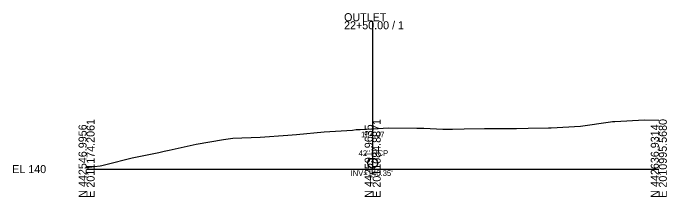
# Model space of a CAD drawing. Extents: x -26 to 1203, y -15 to 9526.
# Drawn here: x 974.3 to 1202.8, y 2490.3 to 2554.4 of the extents above; entities that cross this region are included whole.
import ezdxf

# ---------------------------------------------------------------- set-up
doc = ezdxf.new("R2010")
doc.units = 0
for name, color, linetype in [('Exist Cross Section Cell', 7, 'Continuous'), ('Exist XS Center Line Elevation Label', 7, 'Continuous'), ('Exist XS Ground Line', 7, 'Continuous'), ('Prop XSC Text', 7, 'Continuous')]:
    doc.layers.add(name, color=color, linetype=linetype)

msp = doc.modelspace()

# ---------------------------------------------------------------- linework, layer by layer
at = {"layer": 'Exist Cross Section Cell'}
for p, q in [((1100, 2500), (1100, 2551.58)), ((1000, 2500), (1100, 2500)), ((1100, 2500), (1200, 2500))]:
    msp.add_line(p, q, dxfattribs=at)
at = {"layer": 'Exist XS Ground Line'}
msp.add_lwpolyline([(1000, 2500.6), (1002.71, 2500.91), (1004.71, 2501.15), (1005.37, 2501.23), (1006.68, 2501.56), (1015.9, 2503.96), (1025.26, 2505.85), (1027.1, 2506.25), (1028.92, 2506.66), (1038.3, 2508.75), (1047.8, 2510.31), (1049.49, 2510.59), (1051.16, 2510.77), (1060.69, 2511.16), (1070.35, 2511.87), (1071.88, 2511.99), (1073.4, 2512.11), (1083.08, 2512.97), (1092.9, 2513.64), (1094.28, 2513.76), (1095.63, 2513.83), (1100, 2514.07), (1105.47, 2514.37), (1115.45, 2514.27), (1116.67, 2514.29), (1117.87, 2514.23), (1124.52, 2513.95), (1127.86, 2513.93), (1131.96, 2514.05), (1139.06, 2514.16), (1140.11, 2514.16), (1150.25, 2514.21), (1154.3, 2514.28), (1161.45, 2514.34), (1161.75, 2514.34), (1162.35, 2514.38), (1172.65, 2515.01), (1183.09, 2516.46), (1183.84, 2516.56), (1184.59, 2516.63), (1195.04, 2517.19), (1200, 2517.03)], dxfattribs=at)
at = {"layer": 'Prop XSC Text'}
msp.add_circle((1100, 2502.1), 1.75, dxfattribs=at)

# ---------------------------------------------------------------- texts
at = {"layer": 'Exist Cross Section Cell'}
for s, p in [('OUTLET', (1090, 2551.58)), ('22+50.00 / 1', (1090, 2548.78)), ('EL 140', (974, 2498.6))]:
    msp.add_text(s, height=2.8, dxfattribs=at).set_placement(p)
for s, p in [('E 2011174.2061', (1002.8, 2490)), ('E 2011084.8871', (1102.8, 2490)), ('E 2010995.5680', (1202.8, 2490)), ('N 442546.9956', (1000, 2490)), ('N 442591.9635', (1100, 2490)), ('N 442636.9314', (1200, 2490))]:
    msp.add_text(s, height=2.8, rotation=90, dxfattribs=at).set_placement(p)
at = {"layer": 'Exist XS Center Line Elevation Label'}
msp.add_text('154.07', height=2, dxfattribs=at).set_placement((1095.94, 2511.07))
at = {"layer": 'Prop XSC Text'}
for s, p in [('42" RCP', (1095.09, 2504.57)), ("INV=140.35'", (1092.26, 2497.61))]:
    msp.add_text(s, height=2, dxfattribs=at).set_placement(p)

doc.saveas('drawing.dxf')
